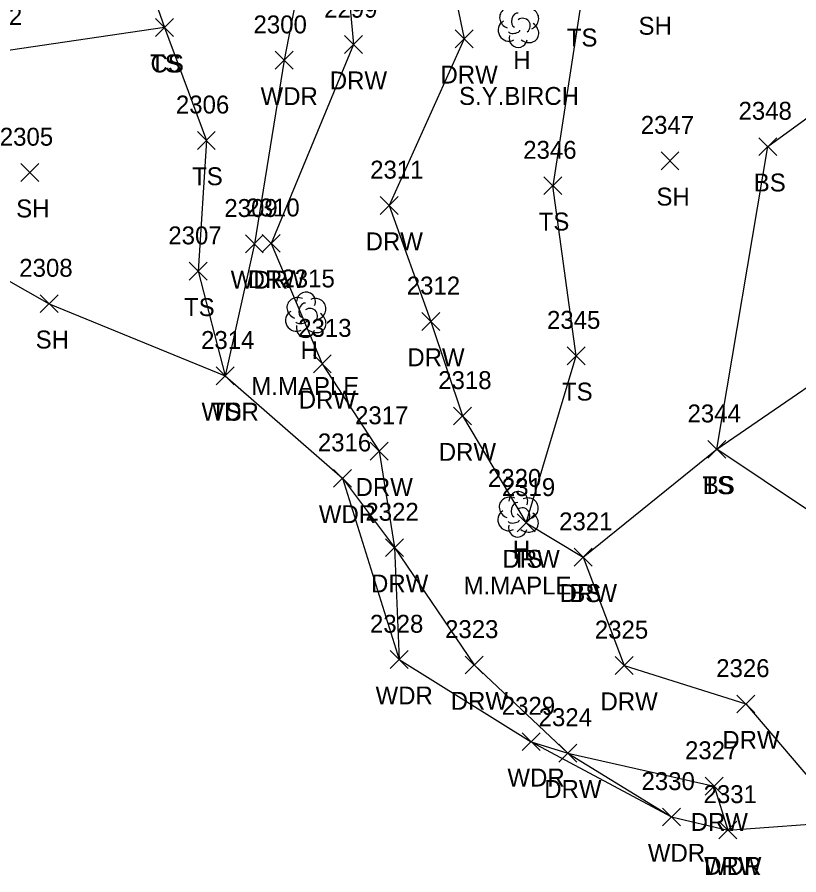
# Model space of a CAD drawing. Extents: x 1512665 to 1513714, y 110636 to 112816.
# Drawn here: x 1512914.5 to 1513001.7, y 110644.5 to 110740.2 of the extents above; entities that cross this region are included whole.
import ezdxf

# ---------------------------------------------------------------- set-up
doc = ezdxf.new("R2010")
doc.units = 0
for name, color, linetype in [('L_A', 7, 'Continuous'), ('L_C', 7, 'Continuous'), ('L_I', 7, 'Continuous'), ('L_TIC', 7, 'Continuous'), ('LAWA', 7, 'Continuous'), ('LELB', 7, 'Continuous'), ('LSOGP', 7, 'Continuous'), ('LTD', 7, 'Continuous'), ('R_A', 7, 'Continuous'), ('R_I', 7, 'Continuous'), ('R_TIC', 7, 'Continuous'), ('RDW', 7, 'Continuous')]:
    doc.layers.add(name, color=color, linetype=linetype)

msp = doc.modelspace()

# ---------------------------------------------------------------- linework, layer by layer
at = {"layer": 'L_TIC'}
for points in [[(1512929.943, 110738.067), (1512931.943, 110740.067)], [(1512931.943, 110738.067), (1512929.943, 110740.067)], [(1512929.943, 110738.067), (1512931.943, 110740.067)], [(1512931.943, 110738.067), (1512929.943, 110740.067)], [(1512943.293, 110734.419), (1512945.293, 110736.419)], [(1512945.293, 110734.419), (1512943.293, 110736.419)], [(1512934.609, 110725.482), (1512936.609, 110727.482)], [(1512936.609, 110725.482), (1512934.609, 110727.482)], [(1512997.215, 110724.784), (1512999.215, 110726.784)], [(1512999.215, 110724.784), (1512997.215, 110726.784)], [(1512986.311, 110723.212), (1512988.311, 110725.212)], [(1512988.311, 110723.212), (1512986.311, 110725.212)], [(1512914.913, 110721.891), (1512916.913, 110723.891)], [(1512916.913, 110721.891), (1512914.913, 110723.891)], [(1512973.26, 110720.428), (1512975.26, 110722.428)], [(1512975.26, 110720.428), (1512973.26, 110722.428)], [(1512973.26, 110720.428), (1512975.26, 110722.428)], [(1512975.26, 110720.428), (1512973.26, 110722.428)], [(1512939.962, 110713.938), (1512941.962, 110715.938)], [(1512941.962, 110713.938), (1512939.962, 110715.938)], [(1512933.709, 110710.884), (1512935.709, 110712.884)], [(1512935.709, 110710.884), (1512933.709, 110712.884)], [(1512917.088, 110707.266), (1512919.088, 110709.266)], [(1512919.088, 110707.266), (1512917.088, 110709.266)], [(1512975.859, 110701.458), (1512977.859, 110703.458)], [(1512977.859, 110701.458), (1512975.859, 110703.458)], [(1512936.713, 110699.214), (1512938.713, 110701.214)], [(1512938.713, 110699.214), (1512936.713, 110701.214)], [(1512936.713, 110699.214), (1512938.713, 110701.214)], [(1512938.713, 110699.214), (1512936.713, 110701.214)], [(1512991.529, 110691.019), (1512993.529, 110693.019)], [(1512993.529, 110691.019), (1512991.529, 110693.019)], [(1512991.529, 110691.019), (1512993.529, 110693.019)], [(1512993.529, 110691.019), (1512991.529, 110693.019)], [(1512949.792, 110687.786), (1512951.792, 110689.786)], [(1512951.792, 110687.786), (1512949.792, 110689.786)], [(1512970.265, 110682.804), (1512972.265, 110684.804)], [(1512972.265, 110682.804), (1512970.265, 110684.804)], [(1512976.643, 110678.977), (1512978.643, 110680.977)], [(1512978.643, 110678.977), (1512976.643, 110680.977)], [(1512956.118, 110667.558), (1512958.118, 110669.558)], [(1512958.118, 110667.558), (1512956.118, 110669.558)], [(1512970.82, 110658.404), (1512972.82, 110660.404)], [(1512972.82, 110658.404), (1512970.82, 110660.404)], [(1512986.484, 110650.003), (1512988.484, 110652.003)], [(1512988.484, 110650.003), (1512986.484, 110652.003)], [(1512992.751, 110648.548), (1512994.751, 110650.548)], [(1512994.751, 110648.548), (1512992.751, 110650.548)]]:
    msp.add_lwpolyline(points, dxfattribs=at)
at = {"layer": 'LAWA'}
msp.add_lwpolyline([(1512904.855, 110814.165), (1512921.132, 110807.474), (1512930.627, 110802.326), (1512939.473, 110793.102), (1512945.641, 110788.646), (1512946.819, 110780.951), (1512948.89, 110763.758), (1512946.989, 110749.434), (1512944.293, 110735.419), (1512940.962, 110714.938), (1512937.713, 110700.214), (1512950.792, 110688.786), (1512957.118, 110668.558), (1512971.82, 110659.404), (1512987.484, 110651.003), (1512993.751, 110649.548)], dxfattribs=at)
at = {"layer": 'LELB'}
for points in [[(1512936.611, 110807.627), (1512953.599, 110791.643), (1512956.195, 110781.418), (1512968.46, 110770.893), (1512974.971, 110752.732), (1512977.394, 110741.958), (1512974.26, 110721.428)], [(1512902.912, 110747.196), (1512898.685, 110764.287), (1512894.988, 110776.221), (1512897.015, 110786.49), (1512915.917, 110779.166), (1512918.439, 110768.088), (1512924.557, 110757.288), (1512930.943, 110739.067), (1512912.467, 110736.35), (1512889.78, 110732.876)], [(1513018.15, 110683.845), (1513008.389, 110681.438), (1512992.529, 110692.019), (1513011.814, 110705.262), (1513019.652, 110718.711), (1513025.66, 110731.752), (1513034.332, 110738.983), (1513039.854, 110744.651), (1513044.439, 110751.049), (1513044.971, 110754.973), (1513045.977, 110758.546)], [(1512977.643, 110679.977), (1512992.529, 110692.019), (1512998.215, 110725.784), (1513009, 110733.662), (1513019.12, 110734.326), (1513034.332, 110738.983), (1513036.177, 110748.289), (1513044.439, 110751.049)], [(1512930.943, 110739.067), (1512935.609, 110726.482), (1512934.709, 110711.884), (1512937.713, 110700.214)], [(1512971.265, 110683.804), (1512976.859, 110702.458), (1512974.26, 110721.428)]]:
    msp.add_lwpolyline(points, dxfattribs=at)
at = {"layer": 'LSOGP'}
msp.add_lwpolyline([(1512896.825, 110720.335), (1512918.085, 110708.265), (1512937.717, 110700.217), (1512950.791, 110688.786), (1512956.603, 110681.05), (1512957.117, 110668.558), (1512971.819, 110659.401), (1512975.923, 110658.133), (1512987.485, 110651.005), (1512993.751, 110649.547), (1513006.943, 110650.517)], dxfattribs=at)
at = {"layer": 'LTD'}
for p, q in [((1512970.4, 110739.44), (1512970.4, 110739.44)), ((1512970.4, 110739.44), (1512970.4, 110739.44)), ((1512946.68, 110707.078), (1512946.68, 110707.078)), ((1512946.68, 110707.078), (1512946.68, 110707.078)), ((1512970.355, 110684.824), (1512970.355, 110684.824)), ((1512970.355, 110684.824), (1512970.355, 110684.824))]:
    msp.add_line(p, q, dxfattribs=at)
for centre in [(1512946.727, 110708.512), (1512970.402, 110686.258)]:
    msp.add_arc(centre, 1.047, 335.52715, 180.95627, dxfattribs=at)
for centre, major_axis, ratio, start_param, end_param in [((1512969.608, 110740.106), (1.21, -0.512), 0.895232, 1.570796, 4.712389), ((1512971.441, 110740.023), (-1.141, -0.483), 0.949671, 1.570796, 4.712389), ((1512970.191, 110739.898), (-0.208, -0.792), 0.645439, 3.141593, 6.283185), ((1512970.9, 110739.273), (-0.5, 0.667), 0.989748, 3.141593, 6.283185), ((1512969.317, 110738.731), (0.584, -1.042), 0.959034, 3.141593, 6.283185), ((1512971.4, 110738.607), (-1.09, 0.792), 0.841452, 1.570796, 4.712389), ((1512970.4, 110737.94), (0.265, 1.061), 0.942809, 1.570796, 4.712389), ((1512969.942, 110738.69), (-0.625, -0.083), 0.423636, 0, 3.141593), ((1512945.888, 110707.744), (1.21, -0.512), 0.895232, 1.570796, 4.712389), ((1512947.721, 110707.661), (-1.141, -0.483), 0.949671, 1.570796, 4.712389), ((1512946.471, 110707.536), (-0.208, -0.792), 0.645439, 3.141593, 6.283185), ((1512947.18, 110706.911), (-0.5, 0.667), 0.989748, 3.141593, 6.283185), ((1512945.597, 110706.369), (0.584, -1.042), 0.959034, 3.141593, 6.283185), ((1512947.68, 110706.245), (-1.09, 0.792), 0.841452, 1.570796, 4.712389), ((1512946.68, 110705.578), (0.265, 1.061), 0.942809, 1.570796, 4.712389), ((1512946.222, 110706.328), (-0.625, -0.083), 0.423636, 0, 3.141593), ((1512969.563, 110685.491), (1.21, -0.512), 0.895232, 1.570796, 4.712389), ((1512971.397, 110685.408), (-1.141, -0.483), 0.949671, 1.570796, 4.712389), ((1512970.147, 110685.282), (-0.208, -0.792), 0.645439, 3.141593, 6.283185), ((1512970.855, 110684.657), (-0.5, 0.667), 0.989748, 3.141593, 6.283185), ((1512969.272, 110684.116), (0.584, -1.042), 0.959034, 3.141593, 6.283185), ((1512971.355, 110683.991), (-1.09, 0.792), 0.841452, 1.570796, 4.712389), ((1512969.897, 110684.074), (-0.625, -0.083), 0.423636, 0, 3.141593), ((1512970.355, 110683.324), (0.265, 1.061), 0.942809, 1.570796, 4.712389)]:
    msp.add_ellipse(centre, major_axis=major_axis, ratio=ratio, start_param=start_param, end_param=end_param, dxfattribs=at)
at = {"layer": 'R_TIC'}
for points in [[(1512951.005, 110736.168), (1512953.005, 110738.168)], [(1512953.005, 110736.168), (1512951.005, 110738.168)], [(1512963.35, 110736.826), (1512965.35, 110738.826)], [(1512965.35, 110736.826), (1512963.35, 110738.826)], [(1512955.004, 110718.217), (1512957.004, 110720.217)], [(1512957.004, 110718.217), (1512955.004, 110720.217)], [(1512941.845, 110713.997), (1512943.845, 110715.997)], [(1512943.845, 110713.997), (1512941.845, 110715.997)], [(1512959.653, 110705.287), (1512961.653, 110707.287)], [(1512961.653, 110705.287), (1512959.653, 110707.287)], [(1512947.542, 110700.566), (1512949.542, 110702.566)], [(1512949.542, 110700.566), (1512947.542, 110702.566)], [(1512963.16, 110694.737), (1512965.16, 110696.737)], [(1512965.16, 110694.737), (1512963.16, 110696.737)], [(1512953.882, 110690.814), (1512955.882, 110692.814)], [(1512955.882, 110690.814), (1512953.882, 110692.814)], [(1512970.265, 110682.804), (1512972.265, 110684.804)], [(1512972.265, 110682.804), (1512970.265, 110684.804)], [(1512955.603, 110680.05), (1512957.603, 110682.05)], [(1512957.603, 110680.05), (1512955.603, 110682.05)], [(1512976.643, 110678.977), (1512978.643, 110680.977)], [(1512978.643, 110678.977), (1512976.643, 110680.977)], [(1512964.489, 110666.959), (1512966.489, 110668.959)], [(1512966.489, 110666.959), (1512964.489, 110668.959)], [(1512981.193, 110666.902), (1512983.193, 110668.902)], [(1512983.193, 110666.902), (1512981.193, 110668.902)], [(1512994.78, 110662.608), (1512996.78, 110664.608)], [(1512996.78, 110662.608), (1512994.78, 110664.608)], [(1512974.923, 110657.132), (1512976.923, 110659.132)], [(1512976.923, 110657.132), (1512974.923, 110659.132)], [(1512991.247, 110653.447), (1512993.247, 110655.447)], [(1512993.247, 110653.447), (1512991.247, 110655.447)], [(1512992.751, 110648.548), (1512994.751, 110650.548)], [(1512994.751, 110648.548), (1512992.751, 110650.548)]]:
    msp.add_lwpolyline(points, dxfattribs=at)
at = {"layer": 'RDW'}
for points in [[(1512900.459, 110800.085), (1512923.203, 110794.904), (1512935.784, 110783.238), (1512946.819, 110780.951), (1512959.698, 110764.789), (1512961.676, 110750.74), (1512964.35, 110737.826), (1512956.004, 110719.217), (1512960.653, 110706.287), (1512964.16, 110695.737), (1512971.265, 110683.804), (1512977.643, 110679.977), (1512982.193, 110667.902), (1512995.78, 110663.608), (1513006.943, 110650.515)], [(1512897.015, 110786.49), (1512918.649, 110784.546), (1512931.904, 110776.206), (1512948.89, 110763.758), (1512950.846, 110750.182), (1512952.005, 110737.168), (1512942.845, 110714.997), (1512948.542, 110701.566), (1512954.882, 110691.814), (1512956.603, 110681.05), (1512965.489, 110667.959), (1512975.923, 110658.132), (1512992.247, 110654.447), (1512993.751, 110649.548)]]:
    msp.add_lwpolyline(points, dxfattribs=at)

# ---------------------------------------------------------------- texts
at = {"layer": 'L_A'}
for s, p in [('SH', (1512983.805, 110738.266)), ('TS', (1512975.804, 110736.958)), ('H', (1512969.833, 110734.44)), ('TS', (1512929.352, 110734.067)), ('CS', (1512929.384, 110734.067)), ('WDR', (1512941.655, 110730.419)), ('TS', (1512934.019, 110721.482)), ('BS', (1512996.655, 110720.784)), ('SH', (1512985.8, 110719.212)), ('SH', (1512914.402, 110717.891)), ('TS', (1512972.669, 110716.428)), ('TS', (1512972.669, 110716.428)), ('WDR', (1512938.325, 110709.938)), ('TS', (1512933.118, 110706.884)), ('SH', (1512916.576, 110703.266)), ('H', (1512946.113, 110702.078)), ('TS', (1512975.268, 110697.458)), ('WDR', (1512935.075, 110695.214)), ('TS', (1512936.122, 110695.214)), ('TS', (1512990.939, 110687.019)), ('BS', (1512990.97, 110687.019)), ('WDR', (1512948.154, 110683.786)), ('H', (1512969.788, 110679.824)), ('TS', (1512969.674, 110678.804)), ('BS', (1512976.084, 110674.977)), ('WDR', (1512954.48, 110663.558)), ('WDR', (1512969.183, 110654.404)), ('WDR', (1512984.846, 110646.003)), ('WDR', (1512991.114, 110644.548))]:
    msp.add_text(s, height=2, dxfattribs=at).set_placement(p)
at = {"layer": 'L_C'}
for s, p in [('S.Y.BIRCH', (1512963.786, 110730.44)), ('M.MAPLE', (1512940.617, 110698.078)), ('M.MAPLE', (1512964.292, 110675.824))]:
    msp.add_text(s, height=2, dxfattribs=at).set_placement(p)
at = {"layer": 'L_I'}
for s, p in [('2302', (1512909.128, 110739.35)), ('2300', (1512940.868, 110738.419)), ('2306', (1512932.215, 110729.482)), ('2348', (1512994.955, 110728.784)), ('2347', (1512984.052, 110727.212)), ('2305', (1512912.575, 110725.891)), ('2346', (1512970.945, 110724.428)), ('2346', (1512970.945, 110724.428)), ('2309', (1512937.616, 110717.938)), ('2307', (1512931.37, 110714.884)), ('2308', (1512914.749, 110711.266)), ('2315', (1512943.987, 110710.078)), ('2345', (1512973.599, 110705.458)), ('2314', (1512935.02, 110703.214)), ('2314', (1512935.02, 110703.214)), ('2344', (1512989.269, 110695.019)), ('2344', (1512989.269, 110695.019)), ('2316', (1512948.044, 110691.786)), ('2320', (1512967.009, 110687.824)), ('2319', (1512968.564, 110686.804)), ('2321', (1512974.95, 110682.977)), ('2328', (1512953.858, 110671.558)), ('2329', (1512968.553, 110662.404)), ('2330', (1512984.137, 110654.003)), ('2331', (1512991.058, 110652.548))]:
    msp.add_text(s, height=2, dxfattribs=at).set_placement(p)
at = {"layer": 'R_A'}
for p in [(1512961.72, 110732.826), (1512949.375, 110732.168), (1512953.374, 110714.217), (1512940.215, 110709.997), (1512958.023, 110701.287), (1512945.912, 110696.566), (1512961.53, 110690.737), (1512952.252, 110686.814), (1512968.635, 110678.804), (1512953.973, 110676.05), (1512975.013, 110674.977), (1512962.859, 110662.959), (1512979.563, 110662.902), (1512993.15, 110658.608), (1512973.293, 110653.132), (1512989.617, 110649.447), (1512991.121, 110644.548)]:
    msp.add_text('DRW', height=2, dxfattribs=at).set_placement(p)
at = {"layer": 'R_I'}
for s, p in [('2299', (1512948.737, 110740.168)), ('2311', (1512953.878, 110722.217)), ('2310', (1512940.066, 110717.997)), ('2312', (1512957.96, 110709.287)), ('2313', (1512945.849, 110704.566)), ('2318', (1512961.467, 110698.737)), ('2317', (1512952.189, 110694.814)), ('2319', (1512968.564, 110686.804)), ('2322', (1512953.344, 110684.05)), ('2321', (1512974.95, 110682.977)), ('2323', (1512962.229, 110670.959)), ('2325', (1512978.934, 110670.902)), ('2326', (1512992.465, 110666.608)), ('2324', (1512972.663, 110661.132)), ('2327', (1512988.987, 110657.447)), ('2331', (1512991.058, 110652.548))]:
    msp.add_text(s, height=2, dxfattribs=at).set_placement(p)

doc.saveas('drawing.dxf')
